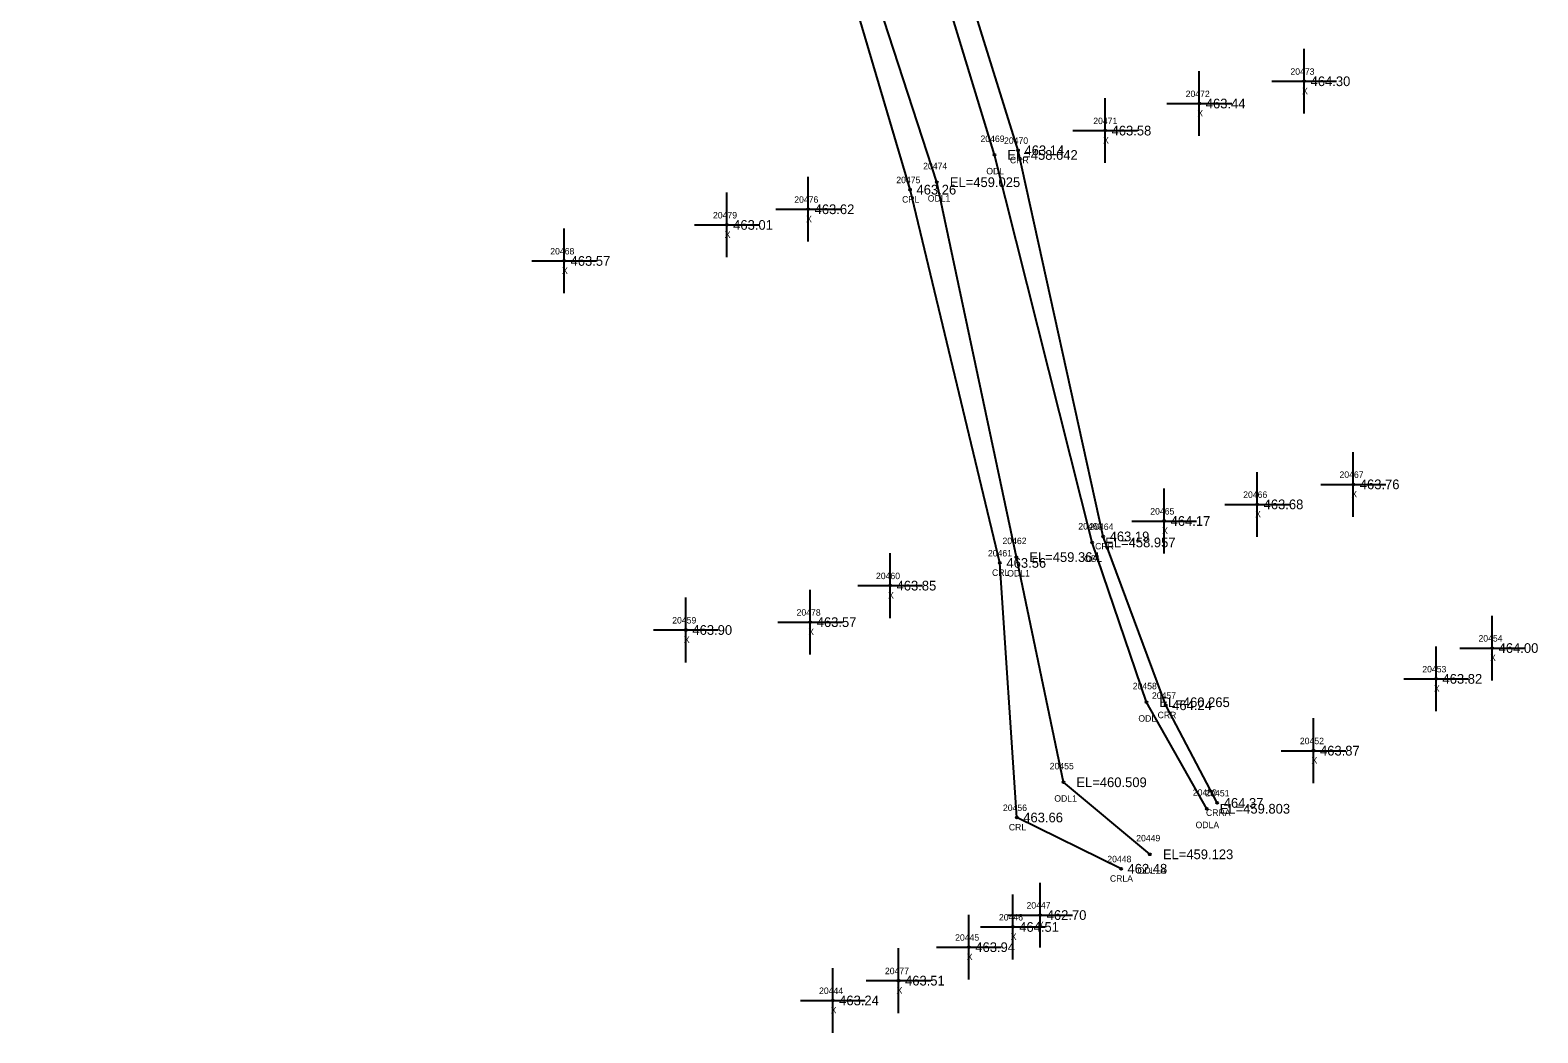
# Model space of a CAD drawing. Extents: x 1785066 to 1786589, y 770293 to 771312.
# Drawn here: x 1785812.9 to 1786045.9, y 770293.2 to 770448 of the extents above; entities that cross this region are included whole.
import ezdxf

# ---------------------------------------------------------------- set-up
doc = ezdxf.new("R2010")
doc.units = 0
for name, color, linetype in [('RD_EX_H2O', 7, 'Continuous'), ('RD_EX_H2O_txCode', 7, 'Continuous'), ('RD_EX_Misc', 7, 'Continuous'), ('RD_EX_Misc_txCode', 7, 'Continuous'), ('RD_EX_TX_H2O_ELEV', 7, 'Continuous'), ('RD_EX_TX_Misc_ELEV', 7, 'Continuous'), ('RD_SMD_Locator', 7, 'Continuous')]:
    doc.layers.add(name, color=color, linetype=linetype)

msp = doc.modelspace()

# ---------------------------------------------------------------- linework, layer by layer
at = {"layer": 'RD_EX_H2O'}
for points in [[(1785996.34, 770328.69), (1785988.37, 770343.77), (1785978.71, 770369.85), (1785965.55, 770429.48), (1785948.02, 770485.76), (1785915.42, 770547.17), (1785885.85, 770601.99), (1785867.88, 770639.76), (1785836.38, 770688.5), (1785826.2, 770733.3), (1785818.95, 770788.69), (1785812.88, 770814.19), (1785823.4, 770822.64)], [(1785994.72, 770327.79), (1785985.4, 770344.24), (1785977.02, 770368.92), (1785961.9, 770428.77), (1785944.95, 770484.4), (1785912.86, 770545.98), (1785881.75, 770600.7), (1785866.13, 770637.95), (1785834.03, 770687.39), (1785820.66, 770730.64), (1785814.87, 770787.58)], [(1785985.94, 770320.75), (1785972.57, 770331.88), (1785965.29, 770366.66), (1785953.01, 770424.56), (1785934.47, 770481.51), (1785902.24, 770538.86), (1785877.7, 770580.42), (1785874.62, 770581.51), (1785874.78, 770574.93), (1785873.42, 770568.8), (1785867.61, 770555.6), (1785846.01, 770529.48), (1785819.4, 770502.95)], [(1785981.47, 770318.52), (1785965.36, 770326.44), (1785962.76, 770365.76), (1785948.86, 770423.41), (1785932.02, 770480.4), (1785898.62, 770537), (1785875.74, 770579.89), (1785875.42, 770579.59), (1785877.36, 770574.13), (1785875.64, 770568.08), (1785869.3, 770551.99), (1785848.15, 770526.89), (1785821.9, 770499.47)]]:
    msp.add_lwpolyline(points, dxfattribs=at)
at = {"layer": 'RD_EX_Misc'}
for p, q in [((1786009.77, 770435.15), (1786009.77, 770445.15)), ((1785993.57, 770431.71), (1785993.57, 770441.71)), ((1786004.77, 770440.15), (1786014.77, 770440.15)), ((1785979.01, 770427.53), (1785979.01, 770437.53)), ((1785988.57, 770436.71), (1785998.57, 770436.71)), ((1785974.01, 770432.53), (1785984.01, 770432.53)), ((1785933.12, 770415.38), (1785933.12, 770425.38)), ((1785920.53, 770412.96), (1785920.53, 770422.96)), ((1785928.12, 770420.38), (1785938.12, 770420.38)), ((1785895.4, 770407.4), (1785895.4, 770417.4)), ((1785915.53, 770417.96), (1785925.53, 770417.96)), ((1785890.4, 770412.4), (1785900.4, 770412.4)), ((1786017.37, 770372.89), (1786017.37, 770382.89)), ((1786002.51, 770369.8), (1786002.51, 770379.8)), ((1785988.13, 770367.23), (1785988.13, 770377.23)), ((1786012.37, 770377.89), (1786022.37, 770377.89)), ((1785997.51, 770374.8), (1786007.51, 770374.8)), ((1785983.13, 770372.23), (1785993.13, 770372.23)), ((1785945.78, 770357.25), (1785945.78, 770367.25)), ((1785914.23, 770350.4), (1785914.23, 770360.4)), ((1785933.44, 770351.61), (1785933.44, 770361.61)), ((1785940.78, 770362.25), (1785950.78, 770362.25)), ((1785928.44, 770356.61), (1785938.44, 770356.61)), ((1786038.83, 770347.61), (1786038.83, 770357.61)), ((1785909.23, 770355.4), (1785919.23, 770355.4)), ((1786030.15, 770342.85), (1786030.15, 770352.85)), ((1786033.83, 770352.61), (1786043.83, 770352.61)), ((1786025.15, 770347.85), (1786035.15, 770347.85)), ((1786011.22, 770331.76), (1786011.22, 770341.76)), ((1786006.22, 770336.76), (1786016.22, 770336.76)), ((1785968.98, 770306.37), (1785968.98, 770316.37)), ((1785964.74, 770304.53), (1785964.74, 770314.53)), ((1785957.95, 770301.41), (1785957.95, 770311.41)), ((1785963.98, 770311.37), (1785973.98, 770311.37)), ((1785959.74, 770309.53), (1785969.74, 770309.53)), ((1785947.09, 770296.24), (1785947.09, 770306.24)), ((1785952.95, 770306.41), (1785962.95, 770306.41)), ((1785936.91, 770293.18), (1785936.91, 770303.18)), ((1785942.09, 770301.24), (1785952.09, 770301.24)), ((1785931.91, 770298.18), (1785941.91, 770298.18))]:
    msp.add_line(p, q, dxfattribs=at)
at = {"layer": 'RD_SMD_Locator'}
for centre in [(1786009.77, 770440.15), (1785993.57, 770436.71), (1785979.01, 770432.53), (1785961.9, 770428.77), (1785965.55, 770429.48), (1785948.86, 770423.41), (1785953.01, 770424.56), (1785933.12, 770420.38), (1785920.53, 770417.96), (1785895.4, 770412.4), (1786017.37, 770377.89), (1786002.51, 770374.8), (1785988.13, 770372.23), (1785978.71, 770369.85), (1785977.02, 770368.92), (1785962.76, 770365.76), (1785965.29, 770366.66), (1785945.78, 770362.25), (1785914.23, 770355.4), (1785933.44, 770356.61), (1786038.83, 770352.61), (1786030.15, 770347.85), (1785985.4, 770344.24), (1785988.37, 770343.77), (1786011.22, 770336.76), (1785972.57, 770331.88), (1785994.72, 770327.79), (1785996.34, 770328.69), (1785965.36, 770326.44), (1785985.94, 770320.75), (1785981.47, 770318.52), (1785968.98, 770311.37), (1785964.74, 770309.53), (1785957.95, 770306.41), (1785947.09, 770301.24), (1785936.91, 770298.18)]:
    msp.add_circle(centre, 0.15, dxfattribs=at)

# ---------------------------------------------------------------- texts
at = {"layer": 'RD_EX_H2O_txCode'}
for s, p in [('20469', (1785959.75, 770430.77)), ('20470', (1785963.39, 770430.48)), ('CRR', (1785964.3, 770427.48)), ('20475', (1785946.74, 770424.41)), ('20474', (1785950.89, 770426.56)), ('ODL', (1785960.65, 770425.77)), ('CRL', (1785947.63, 770421.41)), ('ODL1', (1785951.6, 770421.56)), ('20463', (1785974.87, 770370.92)), ('20464', (1785976.57, 770370.85)), ('20462', (1785963.15, 770368.66)), ('20461', (1785960.9, 770366.76)), ('CRR', (1785977.46, 770367.85)), ('ODL', (1785975.77, 770365.92)), ('CRL', (1785961.53, 770363.76)), ('ODL1', (1785963.88, 770363.66)), ('20458', (1785983.28, 770346.24)), ('20457', (1785986.25, 770344.77)), ('ODL', (1785984.15, 770341.24)), ('CRR', (1785987.12, 770341.77)), ('20455', (1785970.45, 770333.88)), ('ODL1', (1785971.16, 770328.88)), ('20450', (1785992.56, 770329.79)), ('20451', (1785994.51, 770329.69)), ('20456', (1785963.22, 770327.44)), ('CRRA', (1785994.6, 770326.69)), ('CRL', (1785964.13, 770324.44)), ('ODLA', (1785992.99, 770324.79)), ('20449', (1785983.82, 770322.75)), ('20448', (1785979.35, 770319.52)), ('ODL1A', (1785984.04, 770317.75)), ('CRLA', (1785979.75, 770316.52))]:
    msp.add_text(s, height=1, dxfattribs=at).set_placement(p)
at = {"layer": 'RD_EX_Misc_txCode'}
for s, p in [('20473', (1786007.65, 770441.15)), ('20472', (1785991.46, 770437.71)), ('X', (1786009.45, 770438.15)), ('X', (1785993.26, 770434.71)), ('20471', (1785977.18, 770433.53)), ('X', (1785978.7, 770430.53)), ('20476', (1785930.97, 770421.38)), ('20479', (1785918.41, 770418.96)), ('X', (1785932.8, 770418.38)), ('X', (1785920.22, 770415.96)), ('20468', (1785893.26, 770413.4)), ('X', (1785895.08, 770410.4)), ('20467', (1786015.23, 770378.89)), ('20466', (1786000.35, 770375.8)), ('X', (1786017.06, 770375.89)), ('20465', (1785985.99, 770373.23)), ('X', (1786002.2, 770372.8)), ('X', (1785987.82, 770370.23)), ('20460', (1785943.6, 770363.25)), ('X', (1785945.47, 770360.25)), ('20478', (1785931.33, 770357.61)), ('20459', (1785912.11, 770356.4)), ('X', (1785933.13, 770354.61)), ('X', (1785913.91, 770353.4)), ('20454', (1786036.71, 770353.61)), ('X', (1786038.51, 770350.61)), ('20453', (1786028.03, 770348.85)), ('X', (1786029.83, 770345.85)), ('20452', (1786009.11, 770337.76)), ('X', (1786010.91, 770334.76)), ('20446', (1785962.6, 770310.53)), ('20447', (1785966.86, 770312.37)), ('X', (1785968.66, 770309.37)), ('20445', (1785955.83, 770307.41)), ('X', (1785964.42, 770307.53)), ('X', (1785957.63, 770304.41)), ('20477', (1785944.98, 770302.24)), ('20444', (1785934.8, 770299.18)), ('X', (1785946.78, 770299.24)), ('X', (1785936.6, 770296.18))]:
    msp.add_text(s, height=1, dxfattribs=at).set_placement(p)
at = {"layer": 'RD_EX_TX_H2O_ELEV'}
for s, p in [('463.14', (1785966.55, 770428.73)), ('EL=458.642', (1785963.9, 770428.02)), ('463.26', (1785949.86, 770422.66)), ('EL=459.025', (1785955.01, 770423.81)), ('EL=458.957', (1785979.02, 770368.17)), ('463.19', (1785979.71, 770369.1)), ('EL=459.364', (1785967.29, 770365.91)), ('463.56', (1785963.76, 770365.01)), ('EL=460.265', (1785987.4, 770343.49)), ('464.24', (1785989.37, 770343.02)), ('EL=460.509', (1785974.57, 770331.13)), ('EL=459.803', (1785996.72, 770327.04)), ('464.37', (1785997.34, 770327.94)), ('463.66', (1785966.36, 770325.69)), ('EL=459.123', (1785987.94, 770320)), ('462.48', (1785982.47, 770317.77))]:
    msp.add_text(s, height=1.5, dxfattribs=at).set_placement(p)
at = {"layer": 'RD_EX_TX_Misc_ELEV'}
for s, p in [('464.30', (1786010.77, 770439.4)), ('463.44', (1785994.57, 770435.96)), ('463.58', (1785980.01, 770431.78)), ('463.62', (1785934.12, 770419.63)), ('463.01', (1785921.53, 770417.21)), ('463.57', (1785896.4, 770411.65)), ('463.76', (1786018.37, 770377.14)), ('463.68', (1786003.51, 770374.05)), ('464.17', (1785989.13, 770371.48)), ('463.85', (1785946.78, 770361.5)), ('463.90', (1785915.23, 770354.65)), ('463.57', (1785934.44, 770355.86)), ('464.00', (1786039.83, 770351.86)), ('463.82', (1786031.15, 770347.1)), ('463.87', (1786012.22, 770336.01)), ('462.70', (1785969.98, 770310.62)), ('464.51', (1785965.74, 770308.78)), ('463.94', (1785958.95, 770305.66)), ('463.51', (1785948.09, 770300.49)), ('463.24', (1785937.91, 770297.43))]:
    msp.add_text(s, height=1.5, dxfattribs=at).set_placement(p)

doc.saveas('drawing.dxf')
